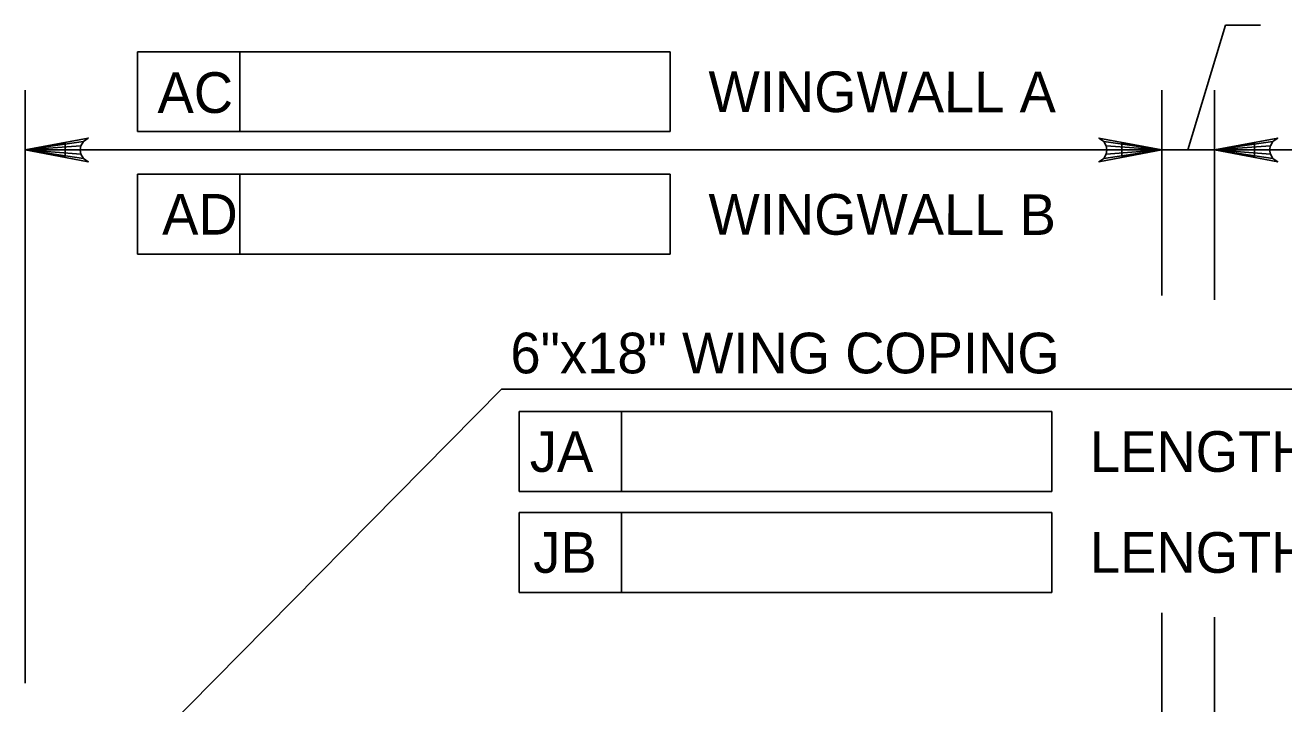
# Model space of a CAD drawing. Extents: x 638304 to 640306, y 296653 to 298435.
# Drawn here: x 638846 to 638938.9, y 296855.2 to 296905.3 of the extents above; entities that cross this region are included whole.
import ezdxf

# ---------------------------------------------------------------- set-up
doc = ezdxf.new("R2010")
doc.units = 0
doc.layers.add('Level 5', color=7, linetype='Continuous')

msp = doc.modelspace()

# ---------------------------------------------------------------- linework, layer by layer
at = {"layer": 'Level 5'}
for p, q in [((638931.818, 296896.104), (638934.582, 296905.313)), ((638934.582, 296905.313), (638937.167, 296905.313)), ((638854.333, 296903.355), (638854.333, 296897.46)), ((638854.333, 296903.355), (638893.627, 296903.355)), ((638861.879, 296903.355), (638861.879, 296897.46)), ((638893.627, 296903.355), (638893.627, 296897.46)), ((638846.034, 296856.76), (638846.034, 296900.525)), ((638929.897, 296885.376), (638929.897, 296900.525)), ((638933.79, 296885.05), (638933.79, 296900.525)), ((638854.333, 296897.46), (638893.627, 296897.46)), ((638846.034, 296896.104), (638929.897, 296896.104)), ((638926.951, 296896.104), (638924.004, 296896.104)), ((638929.897, 296896.104), (638937.68, 296896.104)), ((638933.79, 296896.104), (638939.683, 296896.104)), ((638854.333, 296894.309), (638893.627, 296894.309)), ((638854.333, 296894.309), (638854.333, 296888.414)), ((638861.879, 296894.309), (638861.879, 296888.414)), ((638893.627, 296894.309), (638893.627, 296888.414)), ((638854.333, 296888.414), (638893.627, 296888.414)), ((638853.713, 296850.647), (638881.175, 296878.452)), ((638881.175, 296878.452), (638974.682, 296878.452)), ((638882.477, 296876.801), (638882.477, 296870.906)), ((638882.477, 296876.801), (638921.773, 296876.801)), ((638890.025, 296876.801), (638890.025, 296870.906)), ((638921.773, 296876.801), (638921.773, 296870.906)), ((638882.477, 296870.906), (638921.773, 296870.906)), ((638882.477, 296869.351), (638921.773, 296869.351)), ((638882.477, 296869.351), (638882.477, 296863.456)), ((638890.025, 296869.351), (638890.025, 296863.456)), ((638921.773, 296869.351), (638921.773, 296863.456)), ((638882.477, 296863.456), (638921.773, 296863.456)), ((638929.897, 296849.578), (638929.897, 296861.944)), ((638933.79, 296849.252), (638933.79, 296861.62))]:
    msp.add_line(p, q, dxfattribs=at)
for points in [[(638846.034, 296896.104), (638850.686, 296896.975), (638850.328, 296896.728), (638850.143, 296896.416), (638850.089, 296896.104), (638850.143, 296895.792), (638850.328, 296895.48), (638850.686, 296895.233), (638846.034, 296896.104), (638850.328, 296895.48), (638850.143, 296895.792), (638846.034, 296896.104), (638850.089, 296896.104), (638850.143, 296896.416), (638846.034, 296896.104), (638850.328, 296896.728)], [(638929.897, 296896.104), (638925.246, 296895.233), (638925.603, 296895.48), (638925.788, 296895.792), (638925.842, 296896.104), (638925.788, 296896.416), (638925.603, 296896.728), (638925.246, 296896.975), (638929.897, 296896.104), (638925.603, 296896.728), (638925.788, 296896.416), (638929.897, 296896.104), (638925.842, 296896.104), (638925.788, 296895.792), (638929.897, 296896.104), (638925.603, 296895.48)], [(638933.79, 296896.104), (638938.441, 296896.975), (638938.084, 296896.728), (638937.898, 296896.416), (638937.844, 296896.104), (638937.898, 296895.792), (638938.084, 296895.48), (638938.441, 296895.233), (638933.79, 296896.104), (638938.084, 296895.48), (638937.898, 296895.792), (638933.79, 296896.104), (638937.844, 296896.104), (638937.898, 296896.416), (638933.79, 296896.104), (638938.084, 296896.728)]]:
    msp.add_lwpolyline(points, dxfattribs=at)
for points in [[(638848.981, 296896.595), (638848.981, 296895.611), (638846.034, 296896.104)], [(638926.951, 296896.595), (638926.951, 296895.611), (638929.897, 296896.104)], [(638936.736, 296896.595), (638936.736, 296895.611), (638933.79, 296896.104)]]:
    msp.add_lwpolyline(points, close=True, dxfattribs=at)

# ---------------------------------------------------------------- texts
for s, p in [('AC', (638855.798, 296898.842)), ('WINGWALL A', (638896.442, 296898.906)), ('AD', (638856.139, 296889.865)), ('WINGWALL B', (638896.442, 296889.861))]:
    msp.add_text(s, height=3.0001, rotation=359.93823, dxfattribs=at).set_placement(p)
for s, height, p in [('6"x18" WING COPING', 3.00014, (638881.833, 296879.619)), ('JA', 3.0001, (638883.26, 296872.352)), ('LENGTH WINGWALL A', 3.00014, (638924.588, 296872.352)), ('JB', 3.0001, (638883.516, 296864.902)), ('LENGTH WINGWALL B', 3.00014, (638924.588, 296864.902))]:
    msp.add_text(s, height=height, dxfattribs=at).set_placement(p)

doc.saveas('drawing.dxf')
